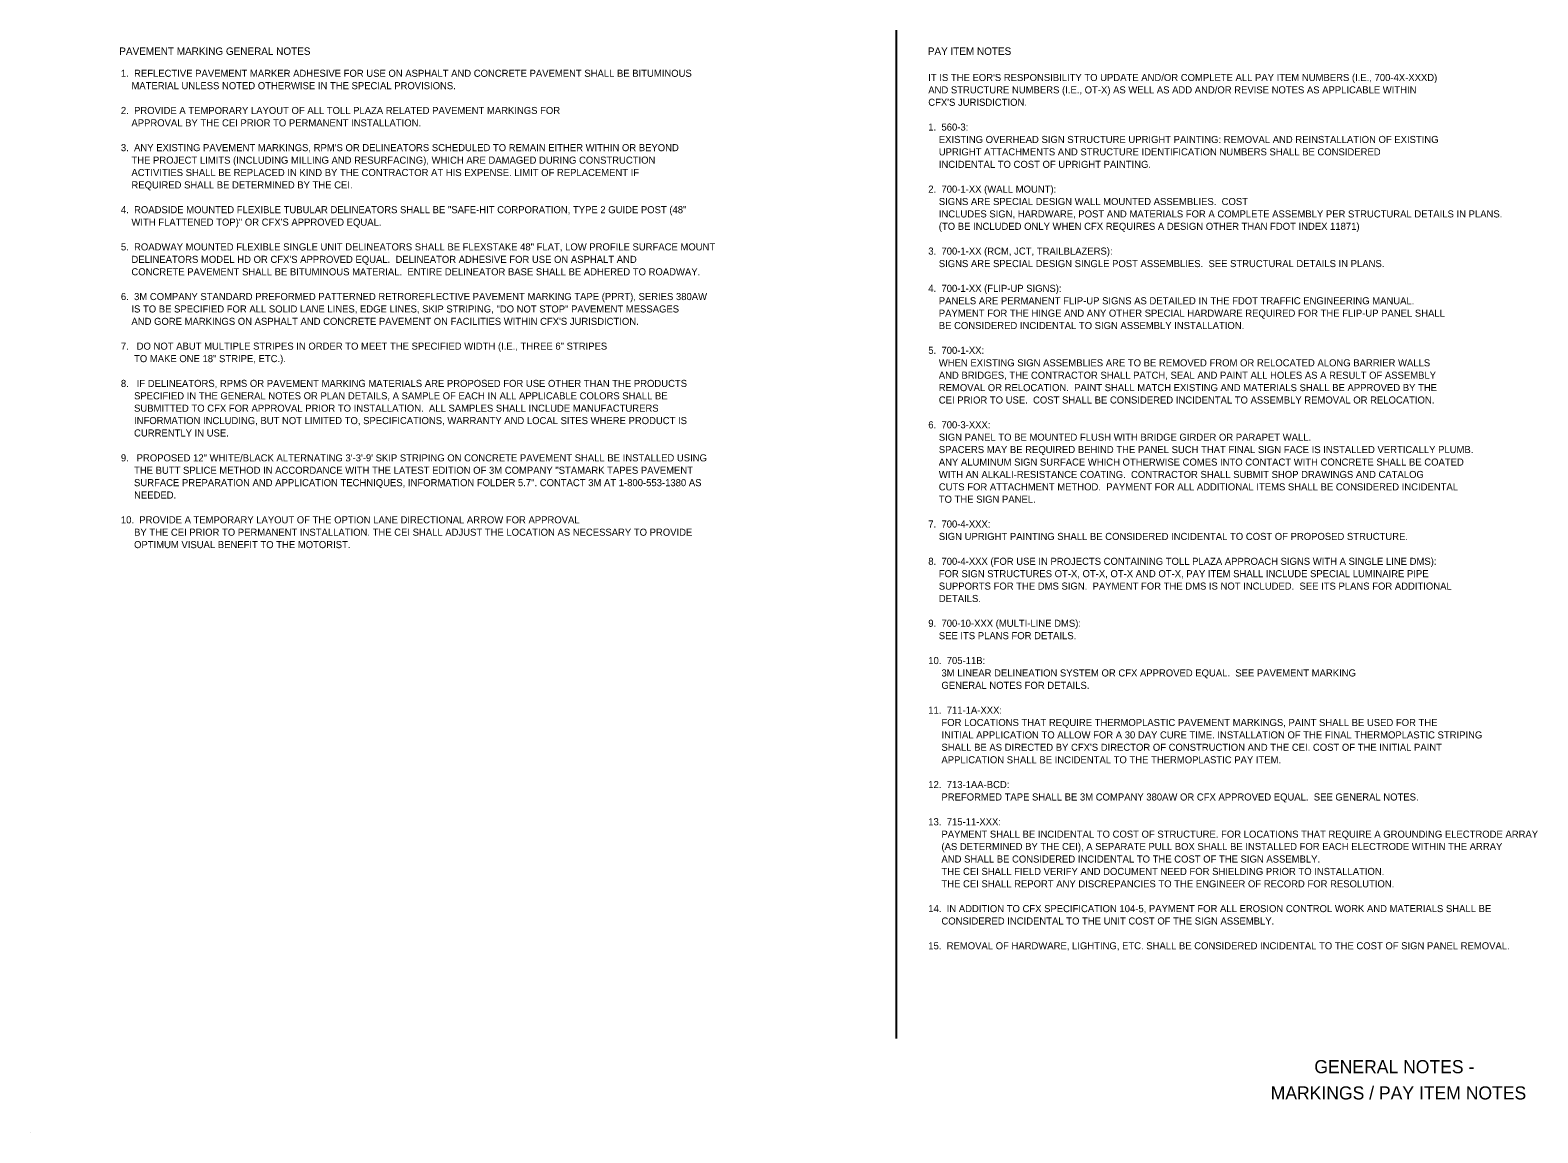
# Model space of a CAD drawing. Extents: x 2479959 to 2482299, y 3677554 to 3678604.
# Drawn here: x 2479959 to 2481395, y 3677554 to 3678604 of the extents above; entities that cross this region are included whole.
import ezdxf

# ---------------------------------------------------------------- set-up
doc = ezdxf.new("R2010")
doc.units = 0
for name, color, linetype in [('AdhocPoint_dp', 7, 'Continuous'), ('NonPlottingEle_dp', 7, 'Continuous'), ('TextLabel', 7, 'Continuous'), ('TextMisc', 7, 'Continuous')]:
    doc.layers.add(name, color=color, linetype=linetype)

msp = doc.modelspace()

# ---------------------------------------------------------------- linework, layer by layer
at = {"layer": 'AdhocPoint_dp'}
msp.add_line((2479959.3, 3677553.8), (2479959.3, 3677553.8), dxfattribs=at)
at = {"layer": 'NonPlottingEle_dp'}
msp.add_line((2480784.3, 3677643.8), (2480784.3, 3678603.8), dxfattribs=at)

# ---------------------------------------------------------------- texts
at = {"layer": 'TextLabel'}
for s, height, p in [('PAVEMENT MARKING GENERAL NOTES', 7.08, (2480044.2, 3678580.3)), ('PAY ITEM NOTES', 7.08, (2480814.2, 3678580.3)), ('1.  REFLECTIVE PAVEMENT MARKER ADHESIVE FOR USE ON ASPHALT AND CONCRETE PAVEMENT SHALL BE BITUMINOUS ', 6.75, (2480045.7, 3678559.4)), ('    MATERIAL UNLESS NOTED OTHERWISE IN THE SPECIAL PROVISIONS.', 6.75, (2480045.7, 3678547.6)), ('AND STRUCTURE NUMBERS (I.E., OT-X) AS WELL AS ADD AND/OR REVISE NOTES AS APPLICABLE WITHIN', 6.75, (2480814.6, 3678543.6)), ("IT IS THE EOR'S RESPONSIBILITY TO UPDATE AND/OR COMPLETE ALL PAY ITEM NUMBERS (I.E., 700-4X-XXXD) ", 6.75, (2480814.6, 3678555.4)), ("CFX'S JURISDICTION.", 6.75, (2480814.6, 3678531.8)), ('2.  PROVIDE A TEMPORARY LAYOUT OF ALL TOLL PLAZA RELATED PAVEMENT MARKINGS FOR ', 6.75, (2480045.7, 3678524)), ('    APPROVAL BY THE CEI PRIOR TO PERMANENT INSTALLATION.', 6.75, (2480045.7, 3678512.2)), ('1.  560-3:', 6.75, (2480814.6, 3678508.2)), ("3.  ANY EXISTING PAVEMENT MARKINGS, RPM'S OR DELINEATORS SCHEDULED TO REMAIN EITHER WITHIN OR BEYOND ", 6.75, (2480045.7, 3678488.6)), ('    EXISTING OVERHEAD SIGN STRUCTURE UPRIGHT PAINTING: REMOVAL AND REINSTALLATION OF EXISTING', 6.75, (2480814.6, 3678496.4)), ('    THE PROJECT LIMITS (INCLUDING MILLING AND RESURFACING), WHICH ARE DAMAGED DURING CONSTRUCTION ', 6.75, (2480045.7, 3678476.7)), ('    UPRIGHT ATTACHMENTS AND STRUCTURE IDENTIFICATION NUMBERS SHALL BE CONSIDERED ', 6.75, (2480814.6, 3678484.6)), ('    INCIDENTAL TO COST OF UPRIGHT PAINTING.', 6.75, (2480814.6, 3678472.7)), ('    ACTIVITIES SHALL BE REPLACED IN KIND BY THE CONTRACTOR AT HIS EXPENSE. LIMIT OF REPLACEMENT IF ', 6.75, (2480045.7, 3678464.9)), ('    REQUIRED SHALL BE DETERMINED BY THE CEI.', 6.75, (2480045.7, 3678453.1)), ('2.  700-1-XX (WALL MOUNT):', 6.75, (2480814.6, 3678449.1)), ('4.  ROADSIDE MOUNTED FLEXIBLE TUBULAR DELINEATORS SHALL BE "SAFE-HIT CORPORATION, TYPE 2 GUIDE POST (48" ', 6.75, (2480045.7, 3678429.5)), ('    SIGNS ARE SPECIAL DESIGN WALL MOUNTED ASSEMBLIES.  COST', 6.75, (2480814.6, 3678437.3)), ('    WITH FLATTENED TOP)" OR CFX\'S APPROVED EQUAL.', 6.75, (2480045.7, 3678417.7)), ('    (TO BE INCLUDED ONLY WHEN CFX REQUIRES A DESIGN OTHER THAN FDOT INDEX 11871)', 6.75, (2480814.6, 3678413.7)), ('    INCLUDES SIGN, HARDWARE, POST AND MATERIALS FOR A COMPLETE ASSEMBLY PER STRUCTURAL DETAILS IN PLANS.', 6.75, (2480814.6, 3678425.5)), ('5.  ROADWAY MOUNTED FLEXIBLE SINGLE UNIT DELINEATORS SHALL BE FLEXSTAKE 48" FLAT, LOW PROFILE SURFACE MOUNT ', 6.75, (2480045.7, 3678394.1)), ('3.  700-1-XX (RCM, JCT, TRAILBLAZERS):', 6.75, (2480814.6, 3678390.1)), ('    CONCRETE PAVEMENT SHALL BE BITUMINOUS MATERIAL.  ENTIRE DELINEATOR BASE SHALL BE ADHERED TO ROADWAY.', 6.75, (2480045.7, 3678370.4)), ("    DELINEATORS MODEL HD OR CFX'S APPROVED EQUAL.  DELINEATOR ADHESIVE FOR USE ON ASPHALT AND", 6.75, (2480045.7, 3678382.2)), ('    SIGNS ARE SPECIAL DESIGN SINGLE POST ASSEMBLIES.  SEE STRUCTURAL DETAILS IN PLANS.', 6.75, (2480814.6, 3678378.2)), ('6.  3M COMPANY STANDARD PREFORMED PATTERNED RETROREFLECTIVE PAVEMENT MARKING TAPE (PPRT), SERIES 380AW', 6.75, (2480045.7, 3678346.8)), ('4.  700-1-XX (FLIP-UP SIGNS):', 6.75, (2480814.6, 3678354.6)), ('    PANELS ARE PERMANENT FLIP-UP SIGNS AS DETAILED IN THE FDOT TRAFFIC ENGINEERING MANUAL.', 6.75, (2480814.6, 3678342.8)), ('    IS TO BE SPECIFIED FOR ALL SOLID LANE LINES, EDGE LINES, SKIP STRIPING, "DO NOT STOP" PAVEMENT MESSAGES', 6.75, (2480045.7, 3678335)), ('    PAYMENT FOR THE HINGE AND ANY OTHER SPECIAL HARDWARE REQUIRED FOR THE FLIP-UP PANEL SHALL', 6.75, (2480814.6, 3678331)), ("    AND GORE MARKINGS ON ASPHALT AND CONCRETE PAVEMENT ON FACILITIES WITHIN CFX'S JURISDICTION.", 6.75, (2480045.7, 3678323.2)), ('    BE CONSIDERED INCIDENTAL TO SIGN ASSEMBLY INSTALLATION.', 6.75, (2480814.6, 3678319.2)), ('7.   DO NOT ABUT MULTIPLE STRIPES IN ORDER TO MEET THE SPECIFIED WIDTH (I.E., THREE 6" STRIPES ', 6.75, (2480045.7, 3678299.6)), ('     TO MAKE ONE 18" STRIPE, ETC.).', 6.75, (2480045.7, 3678287.7)), ('5.  700-1-XX:', 6.75, (2480814.6, 3678295.6)), ('    WHEN EXISTING SIGN ASSEMBLIES ARE TO BE REMOVED FROM OR RELOCATED ALONG BARRIER WALLS', 6.75, (2480814.6, 3678283.7)), ('    AND BRIDGES, THE CONTRACTOR SHALL PATCH, SEAL AND PAINT ALL HOLES AS A RESULT OF ASSEMBLY', 6.75, (2480814.6, 3678271.9)), ('8.   IF DELINEATORS, RPMS OR PAVEMENT MARKING MATERIALS ARE PROPOSED FOR USE OTHER THAN THE PRODUCTS ', 6.75, (2480045.7, 3678264.1)), ('    REMOVAL OR RELOCATION.  PAINT SHALL MATCH EXISTING AND MATERIALS SHALL BE APPROVED BY THE', 6.75, (2480814.6, 3678260.1)), ('     SPECIFIED IN THE GENERAL NOTES OR PLAN DETAILS, A SAMPLE OF EACH IN ALL APPLICABLE COLORS SHALL BE ', 6.75, (2480045.7, 3678252.3)), ('    CEI PRIOR TO USE.  COST SHALL BE CONSIDERED INCIDENTAL TO ASSEMBLY REMOVAL OR RELOCATION.', 6.75, (2480814.6, 3678248.3)), ('     SUBMITTED TO CFX FOR APPROVAL PRIOR TO INSTALLATION.  ALL SAMPLES SHALL INCLUDE MANUFACTURERS ', 6.75, (2480045.7, 3678240.5)), ('     INFORMATION INCLUDING, BUT NOT LIMITED TO, SPECIFICATIONS, WARRANTY AND LOCAL SITES WHERE PRODUCT IS ', 6.75, (2480045.7, 3678228.7)), ('     CURRENTLY IN USE.', 6.75, (2480045.7, 3678216.9)), ('6.  700-3-XXX:', 6.75, (2480814.6, 3678224.7)), ('    SIGN PANEL TO BE MOUNTED FLUSH WITH BRIDGE GIRDER OR PARAPET WALL.   ', 6.75, (2480814.6, 3678212.9)), ('    SPACERS MAY BE REQUIRED BEHIND THE PANEL SUCH THAT FINAL SIGN FACE IS INSTALLED VERTICALLY PLUMB.', 6.75, (2480814.6, 3678201.1)), ('9.   PROPOSED 12" WHITE/BLACK ALTERNATING 3\'-3\'-9\' SKIP STRIPING ON CONCRETE PAVEMENT SHALL BE INSTALLED USING ', 6.75, (2480045.7, 3678193.2)), ('    ANY ALUMINUM SIGN SURFACE WHICH OTHERWISE COMES INTO CONTACT WITH CONCRETE SHALL BE COATED ', 6.75, (2480814.6, 3678189.2)), ('     THE BUTT SPLICE METHOD IN ACCORDANCE WITH THE LATEST EDITION OF 3M COMPANY "STAMARK TAPES PAVEMENT ', 6.75, (2480045.7, 3678181.4)), ('     SURFACE PREPARATION AND APPLICATION TECHNIQUES, INFORMATION FOLDER 5.7". CONTACT 3M AT 1-800-553-1380 AS', 6.75, (2480045.7, 3678169.6)), ('    WITH AN ALKALI-RESISTANCE COATING.  CONTRACTOR SHALL SUBMIT SHOP DRAWINGS AND CATALOG ', 6.75, (2480814.6, 3678177.4)), ('     NEEDED.', 6.75, (2480045.7, 3678157.8)), ('    CUTS FOR ATTACHMENT METHOD.  PAYMENT FOR ALL ADDITIONAL ITEMS SHALL BE CONSIDERED INCIDENTAL', 6.75, (2480814.6, 3678165.6)), ('    TO THE SIGN PANEL.', 6.75, (2480814.6, 3678153.8)), ('10.  PROVIDE A TEMPORARY LAYOUT OF THE OPTION LANE DIRECTIONAL ARROW FOR APPROVAL', 6.75, (2480045.7, 3678134.2)), ('7.  700-4-XXX:', 6.75, (2480814.6, 3678130.2)), ('     BY THE CEI PRIOR TO PERMANENT INSTALLATION. THE CEI SHALL ADJUST THE LOCATION AS NECESSARY TO PROVIDE ', 6.75, (2480045.7, 3678122.4)), ('    SIGN UPRIGHT PAINTING SHALL BE CONSIDERED INCIDENTAL TO COST OF PROPOSED STRUCTURE.', 6.75, (2480814.6, 3678118.4)), ('     OPTIMUM VISUAL BENEFIT TO THE MOTORIST.', 6.75, (2480045.7, 3678110.6)), ('8.  700-4-XXX (FOR USE IN PROJECTS CONTAINING TOLL PLAZA APPROACH SIGNS WITH A SINGLE LINE DMS):', 6.75, (2480814.6, 3678094.7)), ('    SUPPORTS FOR THE DMS SIGN.  PAYMENT FOR THE DMS IS NOT INCLUDED.  SEE ITS PLANS FOR ADDITIONAL', 6.75, (2480814.6, 3678071.1)), ('    FOR SIGN STRUCTURES OT-X, OT-X, OT-X AND OT-X, PAY ITEM SHALL INCLUDE SPECIAL LUMINAIRE PIPE ', 6.75, (2480814.6, 3678082.9)), ('    DETAILS.', 6.75, (2480814.6, 3678059.3)), ('9.  700-10-XXX (MULTI-LINE DMS):', 6.75, (2480814.6, 3678035.7)), ('    SEE ITS PLANS FOR DETAILS.', 6.75, (2480814.6, 3678023.9)), ('10.  705-11B:', 6.75, (2480814.6, 3678000.2)), ('     3M LINEAR DELINEATION SYSTEM OR CFX APPROVED EQUAL.  SEE PAVEMENT MARKING', 6.75, (2480814.6, 3677988.4)), ('     GENERAL NOTES FOR DETAILS.', 6.75, (2480814.6, 3677976.6)), ('11.  711-1A-XXX:', 6.75, (2480814.6, 3677953)), ('     FOR LOCATIONS THAT REQUIRE THERMOPLASTIC PAVEMENT MARKINGS, PAINT SHALL BE USED FOR THE ', 6.75, (2480814.6, 3677941.2)), ('     INITIAL APPLICATION TO ALLOW FOR A 30 DAY CURE TIME. INSTALLATION OF THE FINAL THERMOPLASTIC STRIPING ', 6.75, (2480814.6, 3677929.4)), ("     SHALL BE AS DIRECTED BY CFX'S DIRECTOR OF CONSTRUCTION AND THE CEI. COST OF THE INITIAL PAINT", 6.75, (2480814.6, 3677917.6)), ('     APPLICATION SHALL BE INCIDENTAL TO THE THERMOPLASTIC PAY ITEM.', 6.75, (2480814.6, 3677905.7)), ('12.  713-1AA-BCD:', 6.75, (2480814.6, 3677882.1)), ('     PREFORMED TAPE SHALL BE 3M COMPANY 380AW OR CFX APPROVED EQUAL.  SEE GENERAL NOTES.', 6.75, (2480814.6, 3677870.3)), ('13.  715-11-XXX:', 6.75, (2480814.6, 3677846.7)), ('     PAYMENT SHALL BE INCIDENTAL TO COST OF STRUCTURE. FOR LOCATIONS THAT REQUIRE A GROUNDING ELECTRODE ARRAY ', 6.75, (2480814.6, 3677834.9)), ('     AND SHALL BE CONSIDERED INCIDENTAL TO THE COST OF THE SIGN ASSEMBLY. ', 6.75, (2480814.6, 3677811.2)), ('     (AS DETERMINED BY THE CEI), A SEPARATE PULL BOX SHALL BE INSTALLED FOR EACH ELECTRODE WITHIN THE ARRAY ', 6.75, (2480814.6, 3677823.1)), ('     THE CEI SHALL FIELD VERIFY AND DOCUMENT NEED FOR SHIELDING PRIOR TO INSTALLATION.', 6.75, (2480814.6, 3677799.4)), ('     THE CEI SHALL REPORT ANY DISCREPANCIES TO THE ENGINEER OF RECORD FOR RESOLUTION.', 6.75, (2480814.6, 3677787.6)), ('14.  IN ADDITION TO CFX SPECIFICATION 104-5, PAYMENT FOR ALL EROSION CONTROL WORK AND MATERIALS SHALL BE', 6.75, (2480814.6, 3677764)), ('     CONSIDERED INCIDENTAL TO THE UNIT COST OF THE SIGN ASSEMBLY.', 6.75, (2480814.6, 3677752.2)), ('15.  REMOVAL OF HARDWARE, LIGHTING, ETC. SHALL BE CONSIDERED INCIDENTAL TO THE COST OF SIGN PANEL REMOVAL.', 6.75, (2480814.6, 3677728.6))]:
    msp.add_text(s, height=height, dxfattribs=at).set_placement(p)
at = {"layer": 'TextMisc'}
for s, p in [('    GENERAL NOTES -     ', (2481163.7, 3677610.6)), ('MARKINGS / PAY ITEM NOTES', (2481140.7, 3677585.6))]:
    msp.add_text(s, height=12.5, rotation=360, dxfattribs=at).set_placement(p)

doc.saveas('drawing.dxf')
